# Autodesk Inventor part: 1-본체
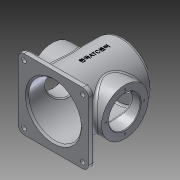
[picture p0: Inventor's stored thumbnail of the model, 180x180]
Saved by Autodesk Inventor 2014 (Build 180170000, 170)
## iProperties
Created: 2015-10
Part Number: 1-본체
Material: 알루미늄 6061
Document SubType Name: Modeling
Designer: Administrator
Density: 2.71 g/cm^3
Appearance: 알루미늄 - 평지
Mass: 984.531 g
Surface Area: 1041.03 cm^2
Volume: 363.296 cm^3
Author: Administrator
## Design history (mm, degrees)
sketch "스케치1"
  geometry: C1 r 50 at (0, 0); 1 further point
  constraints: 1 centre point, 1 coincident
  dimensions: "d0" = 100 diameter of C1
extrude "돌출1" new body sketch "스케치1" distance "d1" = 110; taper "d2" = 0 deg
sketch "스케치2"
  geometry: L1 (-60, 60)-(60, 60); L2 (60, 60)-(60, -60); L3 (60, -60)-(-60, -60); L4 (-60, -60)-(-60, 60); 3 further points
  constraints: 8 end point, 2 midpoint, 2 parallel, 2 perpendicular, 1 horizontal, 1 horizontal alignment, 1 vertical alignment
  dimensions: "d3" = 120 distance of L1.end L2.end
extrude "돌출2" join sketch "스케치2" distance "d4" = 10; taper "d5" = 0 deg
sketch "스케치3"
  geometry: C1 r 40 at (0, 0); 1 further point
  constraints: 1 centre point, 1 coincident
  dimensions: "d6" = 80 diameter of C1
extrude "돌출3" join sketch "스케치3" distance "d7" = 5; taper "d8" = 0 deg
sketch "스케치7"
  geometry: L1 (-10, -60)-(-10, 60) reference; C1 r 40 at (50, 0); 2 further points
  constraints: 1 centre point, 1 horizontal alignment, 1 midpoint
  dimensions: "d19" = 80 diameter of C1; "d20" = 60 distance from line of C1.centre L1
extrude "돌출7" join sketch "스케치7" stored distance "d21" = 124; taper "d22" = 0 deg
sketch "스케치8"
  geometry: C1 r 45 at (0, 0); 1 further point
  constraints: 1 centre point, 1 coincident
  dimensions: "d23" = 90 diameter of C1
extrude "돌출8" cut sketch "스케치8" distance "d24" = 112; taper "d25" = 0 deg
sketch "스케치9"
  geometry: C1 r 27 at (0, 0); 1 further point
  constraints: 1 centre point, 1 coincident
  dimensions: "d26" = 54 diameter of C1
extrude "돌출9" cut sketch "스케치9" distance "d27" = 13; taper "d28" = 0 deg
sketch "스케치10"
  geometry: C1 r 27 at (0, 0); C2 r 40 at (0, 0) reference; 1 further point
  constraints: 1 centre point, 1 concentric
  dimensions: "d29" = 54 diameter of C1
extrude "돌출10" cut sketch "스케치10" stored distance "d30" = 0; taper "d31" = 0 deg
fillet "모깎기1" dims "d32" = 5
fillet "모깎기2" dims "d33" = 5
fillet "모깎기3" dims "d34" = 10
fillet "모깎기4" dims "d35" = 3
chamfer "모따기1" distance "d36" = 3; stored, may be unused: second distance "d37" = 2, angle "d38" = 45 deg
chamfer "모따기2" distance "d39" = 1; stored, may be unused: second distance "d40" = 2, angle "d41" = 45 deg
chamfer "모따기3" distance "d42" = 1; stored, may be unused: second distance "d43" = 2, angle "d44" = 45 deg
chamfer "모따기4" distance "d45" = 1; stored, may be unused: second distance "d46" = 2, angle "d47" = 45 deg
sketch "스케치11"
  geometry: L1 (0, 0)-(22.981, 22.981); L2 (0, 0)-(0, 32.5); A1 r 32.5 centre (0, 0) between (22.981, 22.981) and (0, 32.5); 1 further point
  constraints: 4 end point, 2 point on circle, 1 centre point, 1 coincident, 1 vertical
  dimensions: "d49" = 65 diameter of A1; "d50" = 45 deg angle of L1 L2
hole "구멍1" sketch "스케치11" at (22.981, 22.981) diameter "d51" = 3.242; stored, may be unused: countersink angle "d55" = 90 deg, drill point angle "d57" = 118 deg; dims "d52" = 8, "d53" = 4, "d54" = 2, "d56" = 10
sketch "스케치12"
  geometry: L1 (0, 40)-(0, 0); L2 (0, 0)-(0, -32.5); C1 r 28 at (0, 0) reference; 2 further points
  constraints: 4 end point, 1 collinear, 1 vertical, 1 vertical alignment, 1 other
  dimensions: "d61" = 32.5 distance of L1.end L2.end
hole "구멍2" sketch "스케치12" at (0, -32.5) diameter "d62" = 3.242; stored, may be unused: countersink angle "d66" = 90 deg, drill point angle "d68" = 118 deg; dims "d63" = 8, "d64" = 4, "d65" = 2, "d67" = 10
sketch "스케치13"
  geometry: L1 (0, 28)-(0, 0); L2 (0, 0)-(0, -32.5); C1 r 40 at (0, 0) reference; 1 further point
  constraints: 4 end point, 1 collinear, 1 vertical, 1 vertical alignment, 1 other
  dimensions: "d72" = 32.5 distance of L1.end L2.end
hole "구멍3" sketch "스케치13" at (0, -32.5) diameter "d73" = 3.242; stored, may be unused: countersink angle "d77" = 90 deg, drill point angle "d79" = 118 deg; dims "d74" = 8, "d75" = 4, "d76" = 2, "d78" = 10
sketch "스케치14"
  geometry: L1 (-50, 50)-(50, 50); L2 (50, 50)-(50, -50); L3 (50, -50)-(-50, -50); L4 (-50, -50)-(-50, 50); 3 further points
  constraints: 8 end point, 2 midpoint, 2 parallel, 2 perpendicular, 1 horizontal, 1 horizontal alignment, 1 vertical alignment
  dimensions: "d83" = 100 distance of L1.start L1.end
hole "구멍4" sketch "스케치14" diameter "d84" = 8; stored, may be unused: countersink angle "d88" = 90 deg, drill point angle "d90" = 0 deg; dims "d85" = 8, "d86" = 4, "d87" = 2, "d89" = 10
node "작업 평면1"
sketch "스케치15"
  geometry: L1 (56.398, 35.113)-(56.398, 84.887); L2 (56.398, 84.887)-(63.602, 84.887); L3 (63.602, 84.887)-(63.602, 35.113); L4 (63.602, 35.113)-(56.398, 35.113); L5 (110, -10)-(10, -10) reference; 6 further points
  constraints: 4 midpoint, 2 vertical alignment, 2 other
  dimensions: "d97" = 70 distance from line of L5 point (63.602, 60)
feature "엠보싱1" sketch "스케치15" dims "d98" = 0.5, "d99" = 0
fillet "모깎기5" dims "d100" = 3
node "솔리드1"
pattern_circular "원형 패턴1" dims angle "d59" = 360 deg
pattern_circular "원형 패턴2" dims angle "d70" = 360 deg
pattern_circular "원형 패턴3" dims angle "d81" = 360 deg
pattern_linear "직사각형 패턴1" dims "d93" = 100 (= d83)
node "투영된 루프1"
node "투영된 루프2"
